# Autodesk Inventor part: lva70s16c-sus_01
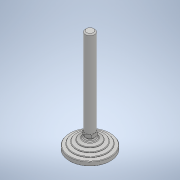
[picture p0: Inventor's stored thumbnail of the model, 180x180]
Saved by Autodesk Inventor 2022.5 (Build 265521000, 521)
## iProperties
Part Number: lva70s16c-sus_01
Material: 一般
Document SubType Name: Modeling
Designer: ImaoCorp
Density: 1 g/cm^3
Appearance: 既定
Author: ImaoCorp
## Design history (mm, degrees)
feature "lva70s16c-sus_01"
node "ソリッド1"
